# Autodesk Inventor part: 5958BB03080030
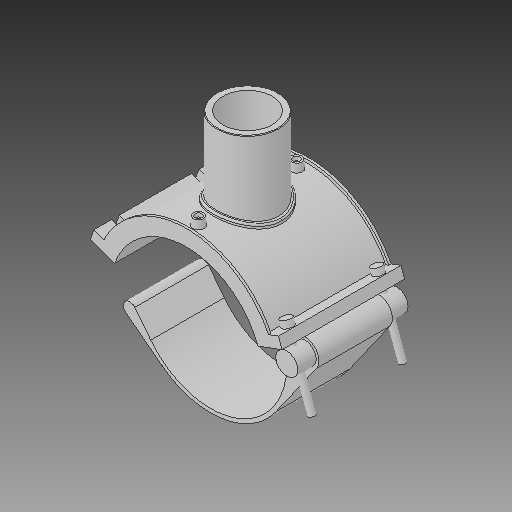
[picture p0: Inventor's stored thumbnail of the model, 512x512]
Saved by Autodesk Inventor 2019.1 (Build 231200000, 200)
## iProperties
Created: 2017-07
Part Number: 5958BB03080030
Material: Generic
Description: PLASSON BRANCH SADDLE 8'' x 3''
Document SubType Name: Modeling
Designer: KIM
Mass: 764.267 g
Surface Area: 1930.38 cm^2
Volume: 764.267 cm^3
Density: 1 g/cm^3
Appearance: Default
Author: KIM
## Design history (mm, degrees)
derived "5958B.ipt"
feature "Solid1::5958B.ipt"
feature "Solid2::5958B.ipt"
feature "Solid3::5958B.ipt"
tag "TaggingFeature1"
body "Solid1"
body "Solid2"
body "Solid3"
other parameters: "d0" = 218.7, "d2" = 233.7816, "d3" = 54.675, "d4" = 176.022, "d5" = 0, "d6" = 0.1, "d8" = 0, "d19" = 6, "d20" = 6, "d21" = 105.6132, "d23" = 0, "d24" = 52.8066, "d26" = 0, "d27" = 3, "d28" = 3, "d29" = 3, "d30" = 72.9, "d31" = 6, "d32" = 0, "d33" = 0, "d34" = 0.6, "d40" = 133.00768, "d41" = 97.57, "d43" = 0, "d45" = 0, "d47" = 234.826, "d48" = 88.7, "d50" = 0, "d70" = 15, "d72" = 0, "d73" = 6, "d75" = 5, "d76" = 0, "d77" = 10.935, "d78" = 139.35, "d79" = 15, "d80" = 70.4088, "d82" = 5 deg, "d84" = 4, "d85" = 14, "d86" = 0, "d87" = 3, "d88" = 0, "d89" = 1, "d90" = 1, "d91" = 140.8176, "d92" = 0, "d93" = 0.5, "d94" = 115.10526, "d96" = 260.89968, "d97" = 3.52044, "d98" = 0, "d102" = 2.661, "d103" = 70.96, "d105" = 0, "d109" = -35.64467, "d117" = 0.887, "d120" = 140 deg, "d121" = 24.228, "d122" = 20 deg, "d123" = 511.568, "d124" = 153.4704, "d126" = 0, "d143" = 229.635, "d150" = 39.366, "d159" = 7.4168, "d161" = 5.4675, "d162" = 105.6132, "d163" = 0, "d167" = 43.74, "d168" = 116.26545, "d173" = 1, "d175" = 109.35, "d176" = 20 deg, "d177" = 15.309, "d178" = 37.084, "d180" = 0, "d185" = 57.20715, "d186" = 57.20715, "d187" = 127.892, "d188" = 11.1252, "d189" = 15.309, "d190" = 0, "d191" = 191.838, "d200" = 18.542, "d202" = 0, "d216" = 158.4198, "d217" = 0, "d221" = 65.12814, "d222" = 15.309, "d223" = 9.1854, "d224" = 109.35, "d225" = 9.1854, "d227" = 31.4928, "d230" = 135.594, "d236" = 11.5 deg, "d238" = 20 deg, "d239" = 15.309, "d240" = 3.52044, "d241" = 0, "d242" = 4.374, "d_" = 218.7, "B_" = 179.832, "H_" = 106.934, "L_" = 176.022, "d_t" = 6, "d_1" = 88.7, "H_1" = 88.392, "d1" = 255.784, "d148" = 5.4675, "d160" = 5.4675
